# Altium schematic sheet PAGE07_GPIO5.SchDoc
size 381 x 381 mm; SheetNumber: 8; SheetTotal: 28
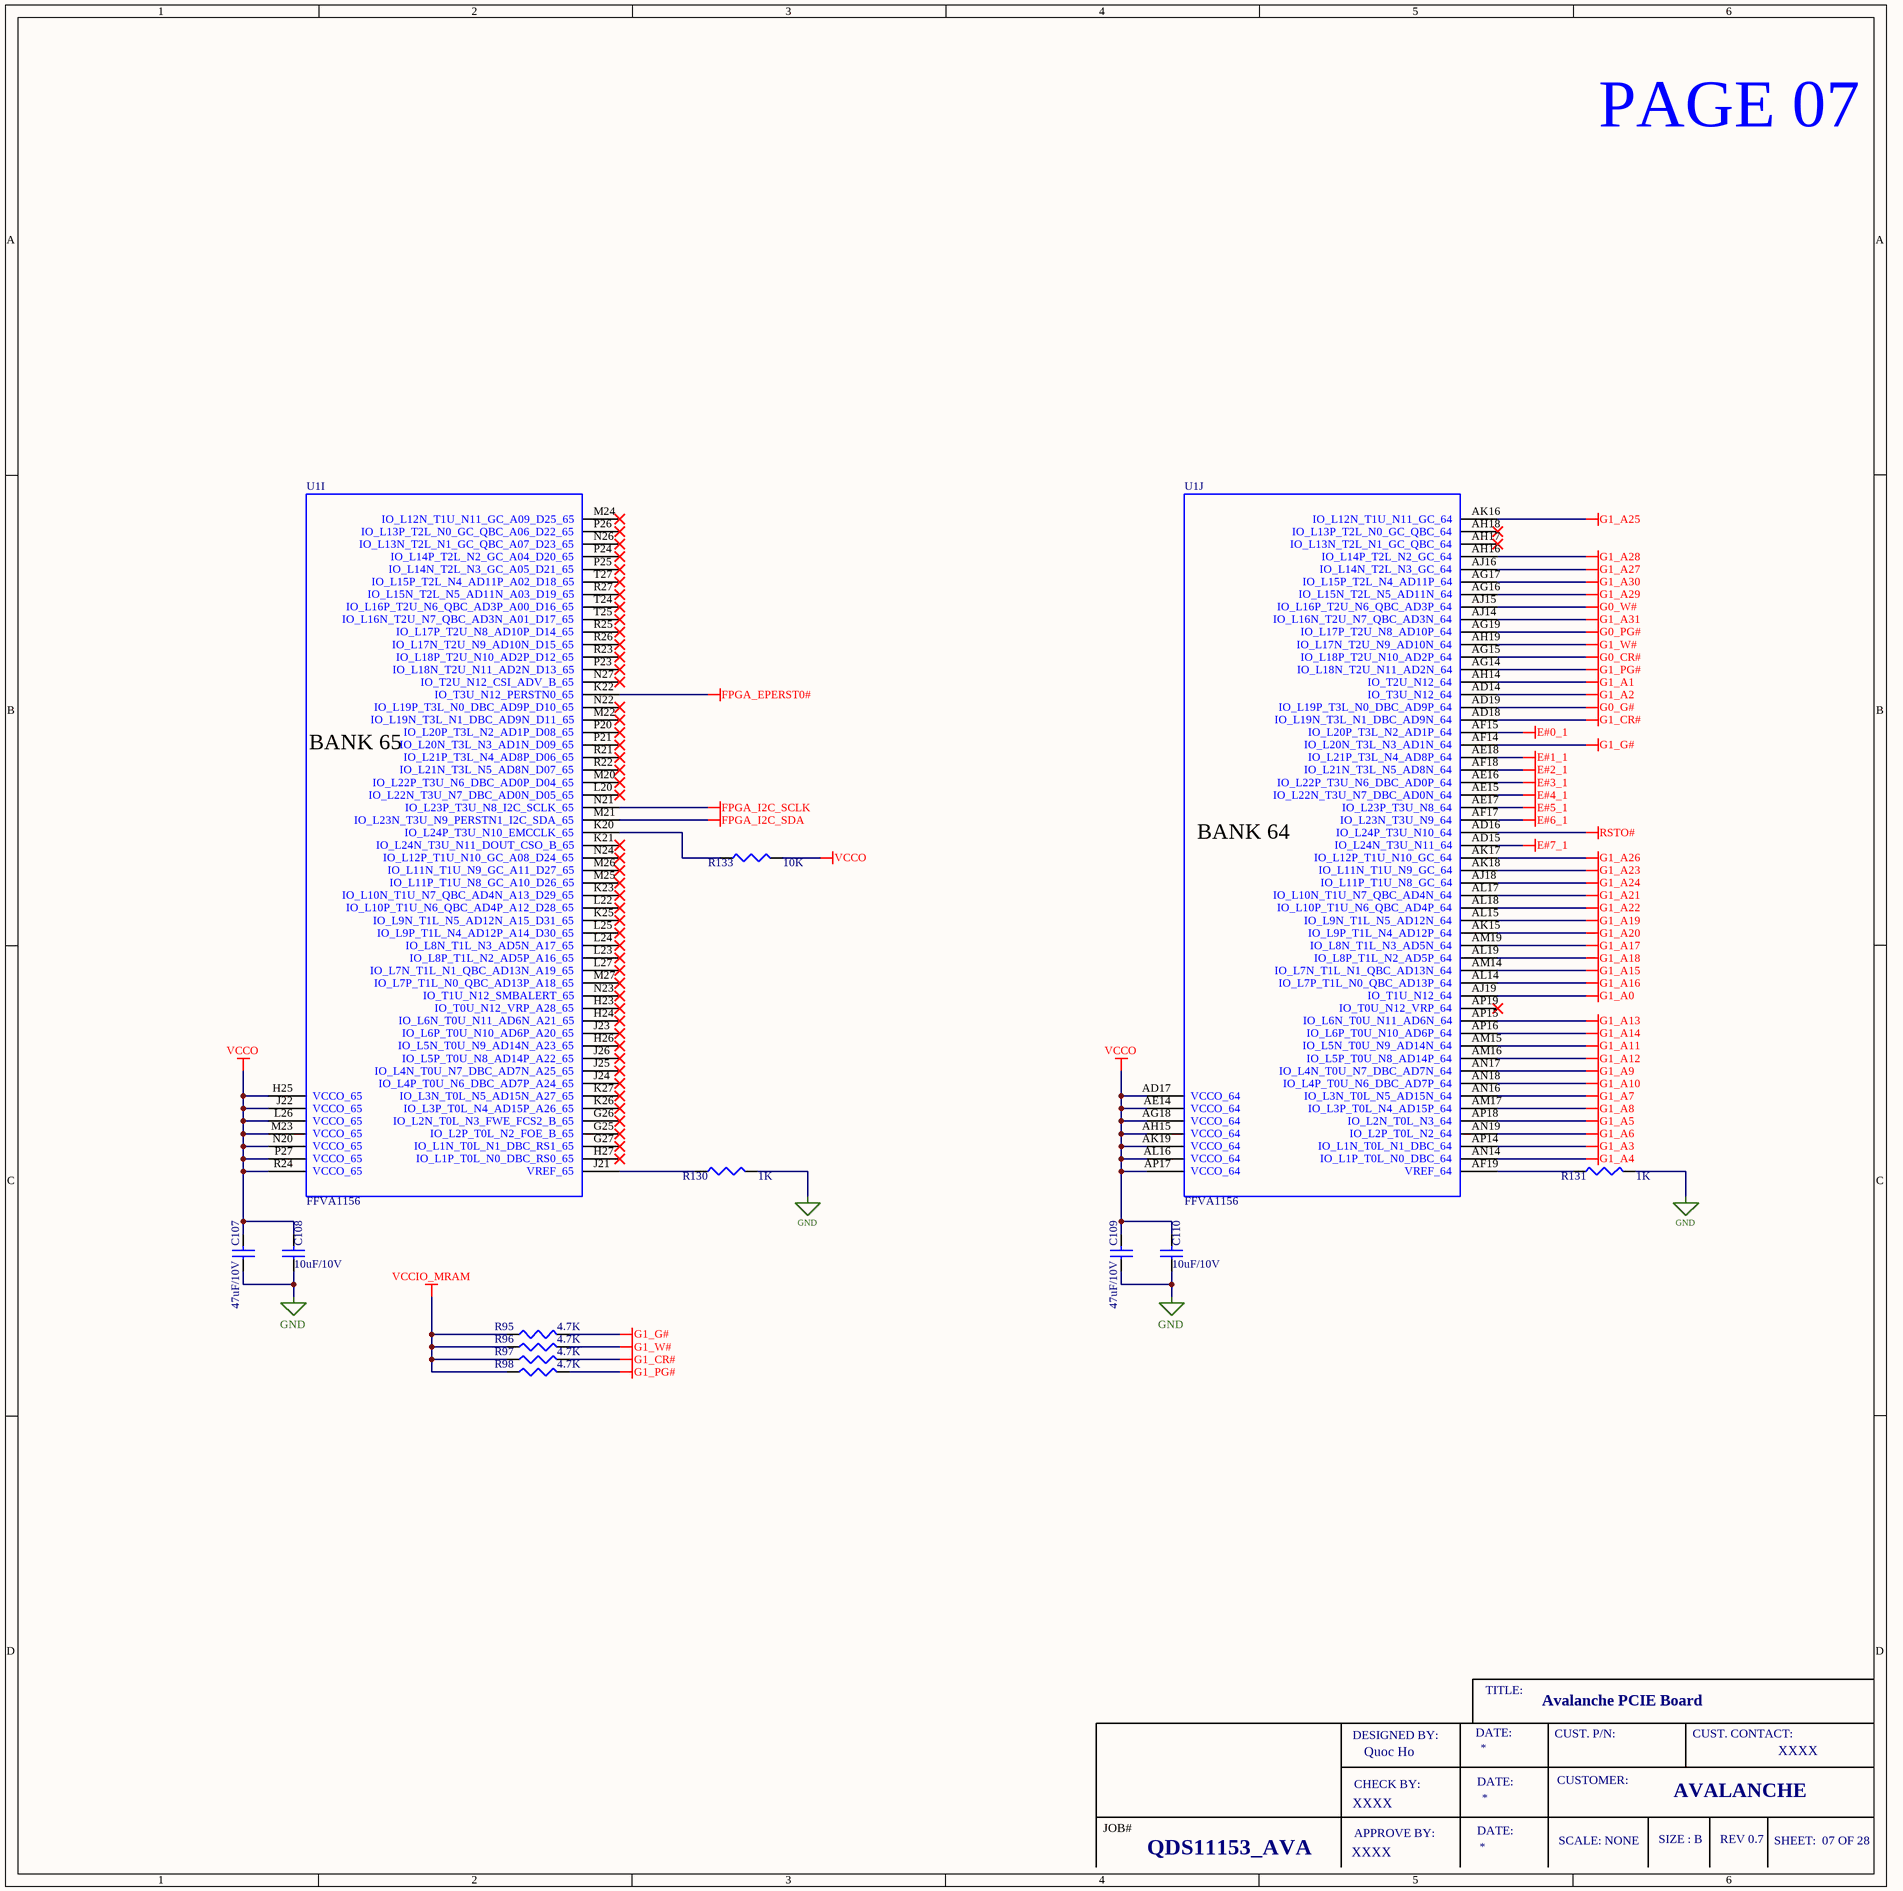
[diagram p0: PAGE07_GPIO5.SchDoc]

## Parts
C107  47uF/10V  [CN_0805]
C108  10uF/10V  [CN_0402]
C109  47uF/10V  [CN_0805]
C110  10uF/10V  [CN_0402]
R95  4.7K  [RN_0402]
R96  4.7K  [RN_0402]
R97  4.7K  [RN_0402]
R98  4.7K  [RN_0402]
R130  1K  [RN_0402]
R131  1K  [RN_0402]
R133  10K  [RN_0402]
U1  FFVA1156  [FFVA1156]  (parts I,J of 25)

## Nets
E#0_1: U1.AF15(IO_L20P_T3L_N2_AD1P_64)
E#1_1: U1.AE18(IO_L21P_T3L_N4_AD8P_64)
E#2_1: U1.AF18(IO_L21N_T3L_N5_AD8N_64)
E#3_1: U1.AE16(IO_L22P_T3U_N6_DBC_AD0P_64)
E#4_1: U1.AE15(IO_L22N_T3U_N7_DBC_AD0N_64)
E#5_1: U1.AE17(IO_L23P_T3U_N8_64)
E#6_1: U1.AF17(IO_L23N_T3U_N9_64)
E#7_1: U1.AD15(IO_L24N_T3U_N11_64)
FPGA_EPERST0#: U1.K22(IO_T3U_N12_PERSTN0_65)
FPGA_I2C_SCLK: U1.N21(IO_L23P_T3U_N8_I2C_SCLK_65)
FPGA_I2C_SDA: U1.M21(IO_L23N_T3U_N9_PERSTN1_I2C_SDA_65)
G0_CR#: U1.AG15(IO_L18P_T2U_N10_AD2P_64)
G0_G#: U1.AD19(IO_L19P_T3L_N0_DBC_AD9P_64)
G0_PG#: U1.AG19(IO_L17P_T2U_N8_AD10P_64)
G0_W#: U1.AJ15(IO_L16P_T2U_N6_QBC_AD3P_64)
G1_A0: U1.AJ19(IO_T1U_N12_64)
G1_A1: U1.AH14(IO_T2U_N12_64)
G1_A2: U1.AD14(IO_T3U_N12_64)
G1_A3: U1.AP14(IO_L1N_T0L_N1_DBC_64)
G1_A4: U1.AN14(IO_L1P_T0L_N0_DBC_64)
G1_A5: U1.AP18(IO_L2N_T0L_N3_64)
G1_A6: U1.AN19(IO_L2P_T0L_N2_64)
G1_A7: U1.AN16(IO_L3N_T0L_N5_AD15N_64)
G1_A8: U1.AM17(IO_L3P_T0L_N4_AD15P_64)
G1_A9: U1.AN17(IO_L4N_T0U_N7_DBC_AD7N_64)
G1_A10: U1.AN18(IO_L4P_T0U_N6_DBC_AD7P_64)
G1_A11: U1.AM15(IO_L5N_T0U_N9_AD14N_64)
G1_A12: U1.AM16(IO_L5P_T0U_N8_AD14P_64)
G1_A13: U1.AP15(IO_L6N_T0U_N11_AD6N_64)
G1_A14: U1.AP16(IO_L6P_T0U_N10_AD6P_64)
G1_A15: U1.AM14(IO_L7N_T1L_N1_QBC_AD13N_64)
G1_A16: U1.AL14(IO_L7P_T1L_N0_QBC_AD13P_64)
G1_A17: U1.AM19(IO_L8N_T1L_N3_AD5N_64)
G1_A18: U1.AL19(IO_L8P_T1L_N2_AD5P_64)
G1_A19: U1.AL15(IO_L9N_T1L_N5_AD12N_64)
G1_A20: U1.AK15(IO_L9P_T1L_N4_AD12P_64)
G1_A21: U1.AL17(IO_L10N_T1U_N7_QBC_AD4N_64)
G1_A22: U1.AL18(IO_L10P_T1U_N6_QBC_AD4P_64)
G1_A23: U1.AK18(IO_L11N_T1U_N9_GC_64)
G1_A24: U1.AJ18(IO_L11P_T1U_N8_GC_64)
G1_A25: U1.AK16(IO_L12N_T1U_N11_GC_64)
G1_A26: U1.AK17(IO_L12P_T1U_N10_GC_64)
G1_A27: U1.AJ16(IO_L14N_T2L_N3_GC_64)
G1_A28: U1.AH16(IO_L14P_T2L_N2_GC_64)
G1_A29: U1.AG16(IO_L15N_T2L_N5_AD11N_64)
G1_A30: U1.AG17(IO_L15P_T2L_N4_AD11P_64)
G1_A31: U1.AJ14(IO_L16N_T2U_N7_QBC_AD3N_64)
G1_CR#: R97.2 U1.AD18(IO_L19N_T3L_N1_DBC_AD9N_64)
G1_G#: R95.2 U1.AF14(IO_L20N_T3L_N3_AD1N_64)
G1_PG#: R98.2 U1.AG14(IO_L18N_T2U_N11_AD2N_64)
G1_W#: R96.2 U1.AH19(IO_L17N_T2U_N9_AD10N_64)
GND: C107.1 C108.1 C109.1 C110.1 R130.2 R131.2
RSTO#: U1.AD16(IO_L24P_T3U_N10_64)
VCCIO_MRAM: R95.1 R96.1 R97.1 R98.1
VCCO: C107.2 C108.2 C109.2 C110.2 R133.2 U1.AD17(VCCO_64) U1.AE14(VCCO_64) U1.AG18(VCCO_64) U1.AH15(VCCO_64) U1.AK19(VCCO_64) U1.AL16(VCCO_64) U1.AP17(VCCO_64) U1.H25(VCCO_65) U1.J22(VCCO_65) U1.L26(VCCO_65) U1.M23(VCCO_65) U1.N20(VCCO_65) U1.P27(VCCO_65) U1.R24(VCCO_65)
NetR130_1: R130.1 U1.J21(VREF_65)
NetR131_1: R131.1 U1.AF19(VREF_64)
NetR133_1: R133.1 U1.K20(IO_L24P_T3U_N10_EMCCLK_65)

Not connected (* = marked no-connect by the designer): U1 AH17(IO_L13N_T2L_N1_GC_QBC_64)* AH18(IO_L13P_T2L_N0_GC_QBC_64)* AP19(IO_T0U_N12_VRP_64)* G25(IO_L2P_T0L_N2_FOE_B_65)* G26(IO_L2N_T0L_N3_FWE_FCS2_B_65)* G27(IO_L1N_T0L_N1_DBC_RS1_65)* H23(IO_T0U_N12_VRP_A28_65)* H24(IO_L6N_T0U_N11_AD6N_A21_65)* H26(IO_L5N_T0U_N9_AD14N_A23_65)* H27(IO_L1P_T0L_N0_DBC_RS0_65)* J23(IO_L6P_T0U_N10_AD6P_A20_65)* J24(IO_L4P_T0U_N6_DBC_AD7P_A24_65)* J25(IO_L4N_T0U_N7_DBC_AD7N_A25_65)* J26(IO_L5P_T0U_N8_AD14P_A22_65)* K21(IO_L24N_T3U_N11_DOUT_CSO_B_65)* K23(IO_L10N_T1U_N7_QBC_AD4N_A13_D29_65)* K25(IO_L9N_T1L_N5_AD12N_A15_D31_65)* K26(IO_L3P_T0L_N4_AD15P_A26_65)* K27(IO_L3N_T0L_N5_AD15N_A27_65)* L20(IO_L22N_T3U_N7_DBC_AD0N_D05_65)* L22(IO_L10P_T1U_N6_QBC_AD4P_A12_D28_65)* L23(IO_L8P_T1L_N2_AD5P_A16_65)* L24(IO_L8N_T1L_N3_AD5N_A17_65)* L25(IO_L9P_T1L_N4_AD12P_A14_D30_65)* L27(IO_L7N_T1L_N1_QBC_AD13N_A19_65)* M20(IO_L22P_T3U_N6_DBC_AD0P_D04_65)* M22(IO_L19N_T3L_N1_DBC_AD9N_D11_65)* M24(IO_L12N_T1U_N11_GC_A09_D25_65)* M25(IO_L11P_T1U_N8_GC_A10_D26_65)* M26(IO_L11N_T1U_N9_GC_A11_D27_65)* M27(IO_L7P_T1L_N0_QBC_AD13P_A18_65)* N22(IO_L19P_T3L_N0_DBC_AD9P_D10_65)* N23(IO_T1U_N12_SMBALERT_65)* N24(IO_L12P_T1U_N10_GC_A08_D24_65)* N26(IO_L13N_T2L_N1_GC_QBC_A07_D23_65)* N27(IO_T2U_N12_CSI_ADV_B_65)* P20(IO_L20P_T3L_N2_AD1P_D08_65)* P21(IO_L20N_T3L_N3_AD1N_D09_65)* P23(IO_L18N_T2U_N11_AD2N_D13_65)* P24(IO_L14P_T2L_N2_GC_A04_D20_65)* P25(IO_L14N_T2L_N3_GC_A05_D21_65)* P26(IO_L13P_T2L_N0_GC_QBC_A06_D22_65)* R21(IO_L21P_T3L_N4_AD8P_D06_65)* R22(IO_L21N_T3L_N5_AD8N_D07_65)* R23(IO_L18P_T2U_N10_AD2P_D12_65)* R25(IO_L17P_T2U_N8_AD10P_D14_65)* R26(IO_L17N_T2U_N9_AD10N_D15_65)* R27(IO_L15N_T2L_N5_AD11N_A03_D19_65)* T24(IO_L16P_T2U_N6_QBC_AD3P_A00_D16_65)* T25(IO_L16N_T2U_N7_QBC_AD3N_A01_D17_65)* T27(IO_L15P_T2L_N4_AD11P_A02_D18_65)*

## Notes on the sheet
- PAGE 07
- (near U1) BANK 65
- (near U1) BANK 64
- TITLE:
- Avalanche PCIE Board
- DESIGNED BY:
- CHECK BY:
- Quoc Ho
- DATE:
- CUST. P/N:
- CUSTOMER:
- CUST. CONTACT:
- XXXX
- JOB#
- APPROVE BY:
- SCALE: NONE
- SIZE : B
- AVALANCHE
- REV 0.7
- SHEET:  07 OF 28
- QDS11153_AVA

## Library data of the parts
C107 C109 = CAP: CAP CER 47UF 10V X5R 0805; Manufacturer Part Number: GRM21BR61A476ME15K; Manufacturer: Murata Electronics
C108 C110 = CAP: CAP CER 10UF 10V X5R 0402; Manufacturer Part Number: GRM155R61A106ME11D; Manufacturer: Murata Electronics
R95-R98 = RES: RES 4.7K OHM 1% 1/16W 0402; Manufacturer Part Number: RC0402FR-134K7L; Manufacturer: YAGEO
R130 R131 = RES: RES 1K OHM 1% 1/16W 0402; Manufacturer Part Number: RC0402FR-131KL; Manufacturer: YAGEO
R133 = RES: RES 10K OHM 1% 1/16W 0402; Manufacturer Part Number: RC0402FR-0710KL; Manufacturer: YAGEO
U1 = FFVA1156: IC FPGA 516 I/O 1156FCBGA; Manufacturer Part Number: XCKU15P-1FFVA1156E; Manufacturer: AMD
